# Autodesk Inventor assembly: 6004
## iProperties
Category: PARTsolutions
Created: 2007-09
Part Number: 6004
Catalog Web Link: www.cadenas.de
Description: Schubstangespanner - 6004 Series
Document SubType Name: Assembly
Designer: PARTsolutions /TMT
NB: 6004
NN: 6004 Series
NT: Straight-Line Action Clamps
NBSYN: $MN.
LINA: 6004
PSOL_MULTISOLIDPART: 0.0
MN: 6004
EDP: 56043
HC: 450
W: 0.81
PT: 1.50
PTH: 5/16-18
A: 106.1
AIN: 4.18
B: 146.6
BIN: 5.77
C: 19.0
CIN: 0.75
D: 22.2
DIN: 0.88
F: 12.7
FIN: 0.50
H: 40.4
HIN: 1.59
J: 3/4-16
K: 6.3
KIN: 0.25
L: 25.4
LIN: 1.00
MPCON: 604106
PPATH: 6004_parts/6004_asmtpl.prj
KT: DUMMY
PSOL_IDENT_0: {\\partserver001.servicenet\dplatte\cadenas\23d-libs\destaco\industries\manual_clamps\straight_line_
PSOL_IDENT_1: action_clamps\through_hole_mount\6004_asmtab.prj},160 {VTYP=3D},{STYP=ASSTAB},{NB=6004},{LINA=6004},
PSOL_IDENT_2: {NN=6004 Series},{DATE=19.06.2006 13:43:59},{GEOMDATE=19.06.2006},{VERSION=},{LINEID=20},{LINESUBID=
PSOL_IDENT_3: -1},{WBVAR=}  {NB=6004},{LINA=6004},{KT=DUMMY},{MN=6004},{EDP=56043},{HC=450},{W=0.81},{PT=1.50},{PT
PSOL_IDENT_4: H=5/16-18},{A=106.1},{AIN=4.18},{B=146.6},{BIN=5.77},{C=19.0},{CIN=0.75},{D=22.2},{DIN=0.88},{F=12.7
PSOL_IDENT_5: },{FIN=0.50},{H=40.4},{HIN=1.59},{J=3/4-16},{K=6.3},{KIN=0.25},{L=25.4},{LIN=1.00},{MPCON=604106},{P
PSOL_IDENT_6: PATH=6004_parts/6004_asmtpl.prj}
Title: 6004
Author: Cadenas PARTsolutions
Comments: DESTACO
